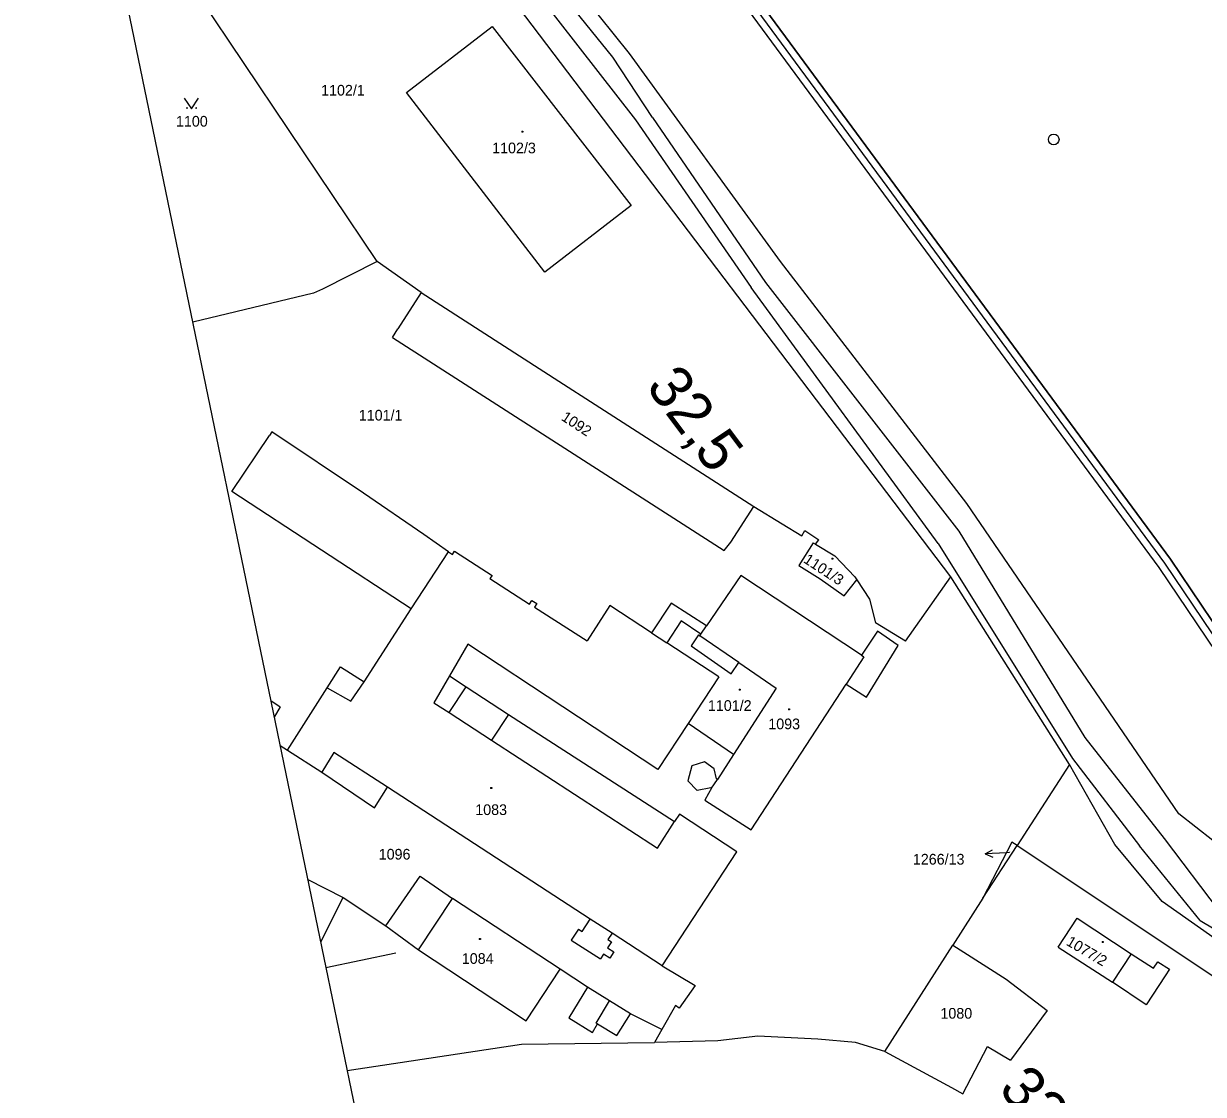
# Model space of a CAD drawing. Extents: x -804166 to -803706, y -1151030 to -1150147.
# Drawn here: x -804166.3 to -804000.6, y -1150430.9 to -1150280.5 of the extents above; entities that cross this region are included whole.
import ezdxf

# ---------------------------------------------------------------- set-up
doc = ezdxf.new("R2010")
doc.units = 0
for name, color, linetype in [('Default', 7, 'Continuous'), ('formát', 7, 'Continuous'), ('kilometráž - vrstava 7', 7, 'Continuous'), ('kn_celek - Cisla parcel pomocna', 7, 'Continuous'), ('kn_celek - Cisla pozemkovych parcel', 7, 'Continuous'), ('kn_celek - Cisla stavebnich parcel', 7, 'Continuous'), ('kn_celek - Hranice parcel', 7, 'Continuous'), ('kn_celek - Vnitrni kresby', 7, 'Continuous'), ('kn_celek - Znacky budov', 7, 'Continuous'), ('kn_celek - Znacky kultur', 7, 'Continuous'), ('plochy - CD', 7, 'Continuous'), ('plochy - VB', 7, 'Continuous'), ('PSR_C2_2_trasa_Vimperk - Kabelová trasa', 7, 'Continuous')]:
    doc.layers.add(name, color=color, linetype=linetype)

# ---------------------------------------------------------------- blocks, each defined once
blk = doc.blocks.new('314')
at = {"layer": 'Default'}
for p, q in [((-10, 15), (0, 0)), ((0, 0), (10, 15))]:
    blk.add_line(p, q, dxfattribs=at)
for centre, start, end in [((-6.2, 1), 360, 180), ((-6.2, 1), 180, 360), ((6.6, 1), 0, 180), ((6.6, 1), 180, 0)]:
    blk.add_arc(centre, 0.5, start, end, dxfattribs=at)
blk = doc.blocks.new('402')
at = {"layer": 'Default'}
for p, q in [((-0.8, 0.8), (0.7, 0.8)), ((-0.8, 0.8), (-0.8, -0.7)), ((0.7, 0.8), (0.7, -0.7)), ((0.7, -0.7), (-0.8, -0.7))]:
    blk.add_line(p, q, dxfattribs=at)
blk = doc.blocks.new('Z61')
at = {"layer": 'Default'}
for p, q in [((0, 0), (30, 0)), ((30, 0), (19.2, 5.3)), ((30, 0), (19.2, -5.3))]:
    blk.add_line(p, q, dxfattribs=at)

msp = doc.modelspace()

# ---------------------------------------------------------------- linework, layer by layer
at = {"layer": 'formát'}
for p, q in [((-804166.3, -1150207.4), (-804123.84, -1150413.06)), ((-804123.84, -1150413.06), (-804114.04, -1150411.04)), ((-804123.84, -1150413.06), (-804081.38, -1150618.72))]:
    msp.add_line(p, q, dxfattribs=at)
at = {"layer": 'kilometráž - vrstava 7'}
msp.add_circle((-804021.64, -1150296.75), 0.75, dxfattribs=at)
at = {"layer": 'kn_celek - Cisla parcel pomocna'}
msp.add_line((-804027.84, -1150396.94), (-804028.28, -1150396.96), dxfattribs=at)
at = {"layer": 'kn_celek - Hranice parcel'}
for p, q in [((-804081.21, -1150284.7), (-804121.35, -1150234.4)), ((-804116.64, -1150313.9), (-804155.03, -1150256.65)), ((-804036.11, -1150358.19), (-804098.91, -1150275.35)), ((-804112.54, -1150290.16), (-804100.49, -1150280.89)), ((-804100.49, -1150280.89), (-804080.97, -1150306.02)), ((-804060.01, -1150313.9), (-804081.21, -1150284.7)), ((-804093.08, -1150315.42), (-804112.54, -1150290.16)), ((-804080.97, -1150306.02), (-804093.08, -1150315.42)), ((-804116.64, -1150313.9), (-804124.3, -1150317.79)), ((-804110.46, -1150318.24), (-804116.64, -1150313.9)), ((-804033.86, -1150347.88), (-804060.01, -1150313.9)), ((-804124.3, -1150317.79), (-804125.6, -1150318.34)), ((-804125.6, -1150318.34), (-804142.55, -1150322.43)), ((-804110.46, -1150318.24), (-804113.74, -1150323.38)), ((-804110.46, -1150318.24), (-804090.5, -1150331.11)), ((-804114.51, -1150324.58), (-804113.74, -1150323.38)), ((-804114.51, -1150324.58), (-804067.92, -1150354.52)), ((-804090.5, -1150331.11), (-804086.7, -1150333.56)), ((-804086.7, -1150333.56), (-804063.77, -1150348.34)), ((-804137.05, -1150346.23), (-804131.77, -1150338.33)), ((-804131.45, -1150337.85), (-804131.77, -1150338.33)), ((-804118.57, -1150346.46), (-804131.45, -1150337.85)), ((-804111.88, -1150362.71), (-804137.05, -1150346.23)), ((-804110.08, -1150352.27), (-804118.57, -1150346.46)), ((-804066.98, -1150353.34), (-804063.77, -1150348.34)), ((-804063.77, -1150348.34), (-804059.77, -1150350.77)), ((-804004.05, -1150391.51), (-804033.86, -1150347.88)), ((-804059.77, -1150350.77), (-804057.02, -1150352.44)), ((-804106.65, -1150354.7), (-804110.08, -1150352.27)), ((-804057.02, -1150352.44), (-804056.61, -1150351.71)), ((-804056.61, -1150351.71), (-804054.61, -1150353.01)), ((-804067.92, -1150354.52), (-804066.98, -1150353.34)), ((-804055.41, -1150353.41), (-804057.43, -1150356.6)), ((-804055.41, -1150353.41), (-804055.07, -1150353.62)), ((-804055.07, -1150353.62), (-804054.61, -1150353.01)), ((-804055.07, -1150353.62), (-804052.39, -1150355.25)), ((-804106.65, -1150354.7), (-804106.08, -1150355.06)), ((-804106.08, -1150355.06), (-804105.79, -1150354.6)), ((-804105.79, -1150354.6), (-804100.51, -1150357.99)), ((-804049.55, -1150358.18), (-804052.39, -1150355.25)), ((-804057.43, -1150356.6), (-804054.44, -1150358.5)), ((-804100.51, -1150357.99), (-804100.81, -1150358.45)), ((-804100.81, -1150358.45), (-804095.25, -1150362.02)), ((-804065.57, -1150358), (-804070.4, -1150365.1)), ((-804048.65, -1150369.22), (-804065.57, -1150358)), ((-804054.44, -1150358.5), (-804051.06, -1150360.86)), ((-804051.06, -1150360.86), (-804049.27, -1150358.61)), ((-804049.55, -1150358.18), (-804049.27, -1150358.61)), ((-804049.27, -1150358.61), (-804047.52, -1150361.32)), ((-804042.43, -1150367.25), (-804036.11, -1150358.19)), ((-804019.43, -1150384.54), (-804036.11, -1150358.19)), ((-804095.25, -1150362.02), (-804094.92, -1150361.51)), ((-804094.92, -1150361.51), (-804094.22, -1150361.96)), ((-804094.22, -1150361.96), (-804094.55, -1150362.47)), ((-804094.55, -1150362.47), (-804087.17, -1150367.2)), ((-804083.95, -1150362.23), (-804087.17, -1150367.2)), ((-804078.13, -1150366.07), (-804083.95, -1150362.23)), ((-804075.36, -1150361.89), (-804078.13, -1150366.07)), ((-804070.4, -1150365.1), (-804075.36, -1150361.89)), ((-804047.52, -1150361.32), (-804046.65, -1150364.68)), ((-804118.45, -1150372.97), (-804111.88, -1150362.71)), ((-804071.18, -1150366.26), (-804070.4, -1150365.1)), ((-804046.4, -1150365.83), (-804048.65, -1150369.22)), ((-804042.43, -1150367.25), (-804046.65, -1150364.68)), ((-804043.46, -1150367.86), (-804046.4, -1150365.83)), ((-804078.13, -1150366.07), (-804075.97, -1150367.48)), ((-804068.66, -1150372.26), (-804075.97, -1150367.48)), ((-804071.53, -1150366.35), (-804072.53, -1150367.9)), ((-804071.53, -1150366.35), (-804071.33, -1150366.49)), ((-804071.33, -1150366.49), (-804071.18, -1150366.26)), ((-804103.93, -1150367.66), (-804106.49, -1150372.1)), ((-804077.23, -1150385.27), (-804103.93, -1150367.66)), ((-804072.53, -1150367.9), (-804066.93, -1150371.81)), ((-804047.95, -1150375.09), (-804043.46, -1150367.86)), ((-804123.67, -1150373.78), (-804121.79, -1150370.84)), ((-804121.79, -1150370.84), (-804118.45, -1150372.97)), ((-804066.93, -1150371.81), (-804065.85, -1150370.25)), ((-804065.85, -1150370.25), (-804060.62, -1150373.84)), ((-804106.49, -1150372.1), (-804104.14, -1150373.65)), ((-804068.66, -1150372.26), (-804072.97, -1150378.81)), ((-804129.25, -1150382.55), (-804123.67, -1150373.78)), ((-804104.14, -1150373.65), (-804098.21, -1150377.56)), ((-804060.62, -1150373.84), (-804066.6, -1150383.18)), ((-804064.14, -1150393.75), (-804050.8, -1150373.27)), ((-804050.8, -1150373.27), (-804047.95, -1150375.09)), ((-804131.58, -1150375.58), (-804130.27, -1150376.47)), ((-804130.27, -1150376.47), (-804131.1, -1150377.9)), ((-804098.21, -1150377.56), (-804074.88, -1150392.59)), ((-804072.97, -1150378.81), (-804077.23, -1150385.27)), ((-804066.6, -1150383.18), (-804072.97, -1150378.81)), ((-804130.27, -1150381.91), (-804129.25, -1150382.55)), ((-804129.25, -1150382.55), (-804124.41, -1150385.63)), ((-804070.69, -1150384.19), (-804072.47, -1150384.76)), ((-804069.32, -1150385.17), (-804070.69, -1150384.19)), ((-804066.6, -1150383.18), (-804068.84, -1150386.68)), ((-804124.41, -1150385.63), (-804117.01, -1150390.65)), ((-804072.47, -1150384.76), (-804073.03, -1150386.88)), ((-804068.99, -1150386.56), (-804069.32, -1150385.17)), ((-804019.43, -1150384.54), (-804026.79, -1150395.95)), ((-804013.04, -1150395.78), (-804019.43, -1150384.54)), ((-804073.03, -1150386.88), (-804071.69, -1150388.23)), ((-804068.84, -1150386.68), (-804068.99, -1150386.56)), ((-804117.01, -1150390.65), (-804115.18, -1150387.77)), ((-804086.74, -1150406.28), (-804115.18, -1150387.77)), ((-804069.79, -1150387.85), (-804071.69, -1150388.23)), ((-804070.1, -1150388.62), (-804070.63, -1150389.59)), ((-804069.7, -1150387.9), (-804070.1, -1150388.62)), ((-804069.79, -1150387.85), (-804069.7, -1150387.9)), ((-804070.63, -1150389.59), (-804064.14, -1150393.75)), ((-804074.21, -1150391.55), (-804074.88, -1150392.59)), ((-804066.12, -1150396.82), (-804074.21, -1150391.55)), ((-803965.92, -1150421.41), (-804004.05, -1150391.51)), ((-804027.51, -1150395.47), (-804031.57, -1150403.35)), ((-804026.79, -1150395.95), (-804027.51, -1150395.47)), ((-804006.42, -1150403.82), (-804013.04, -1150395.78)), ((-804076.63, -1150412.86), (-804066.12, -1150396.82)), ((-804031.57, -1150403.35), (-804026.79, -1150395.95)), ((-804026.79, -1150395.95), (-803971.47, -1150432.84)), ((-804126.38, -1150400.74), (-804121.43, -1150403.27)), ((-804115.43, -1150407.21), (-804110.61, -1150400.26)), ((-804110.61, -1150400.26), (-804106.05, -1150403.38)), ((-804121.43, -1150403.27), (-804115.43, -1150407.21)), ((-804090.94, -1150413.32), (-804106.05, -1150403.38)), ((-804031.57, -1150403.35), (-804035.79, -1150409.93)), ((-803984.95, -1150418.93), (-804006.42, -1150403.82)), ((-804087.86, -1150408.01), (-804086.74, -1150406.28)), ((-804021.01, -1150410.24), (-804018.34, -1150406.17)), ((-804018.34, -1150406.17), (-804010.77, -1150411.14)), ((-804088.38, -1150407.69), (-804089.38, -1150409.22)), ((-804088.38, -1150407.69), (-804087.86, -1150408.01)), ((-804083.66, -1150408.28), (-804084.25, -1150409.15)), ((-804076.63, -1150412.86), (-804083.66, -1150408.28)), ((-804089.38, -1150409.22), (-804085.28, -1150411.85)), ((-804083.76, -1150409.47), (-804084.3, -1150410.32)), ((-804084.3, -1150410.32), (-804083.42, -1150410.88)), ((-804084.25, -1150409.15), (-804083.76, -1150409.47)), ((-804045.36, -1150424.86), (-804035.79, -1150409.93)), ((-804035.79, -1150409.93), (-804034.24, -1150410.92)), ((-804021.01, -1150410.24), (-804013.4, -1150415.15)), ((-804084.86, -1150411.19), (-804085.28, -1150411.85)), ((-804083.98, -1150411.75), (-804084.86, -1150411.19)), ((-804083.42, -1150410.88), (-804083.98, -1150411.75)), ((-804034.24, -1150410.92), (-804028.34, -1150414.7)), ((-804010.77, -1150411.14), (-804007.61, -1150413.19)), ((-804007.61, -1150413.19), (-804007.01, -1150412.27)), ((-804007.01, -1150412.27), (-804005.4, -1150413.32)), ((-804087.12, -1150415.83), (-804090.94, -1150413.32)), ((-804076.63, -1150412.86), (-804071.97, -1150415.6)), ((-804005.4, -1150413.32), (-804006.01, -1150414.26)), ((-804071.97, -1150415.6), (-804074.24, -1150418.81)), ((-804028.34, -1150414.7), (-804022.57, -1150419.14)), ((-804008.66, -1150418.32), (-804013.4, -1150415.15)), ((-804006.01, -1150414.26), (-804008.66, -1150418.32)), ((-804084, -1150417.78), (-804087.12, -1150415.83)), ((-804081.08, -1150419.61), (-804084, -1150417.78)), ((-804074.74, -1150418.43), (-804076.66, -1150421.77)), ((-804074.24, -1150418.81), (-804074.74, -1150418.43)), ((-804076.66, -1150421.77), (-804081.08, -1150419.61)), ((-804022.57, -1150419.14), (-804027.7, -1150426.08)), ((-804076.66, -1150421.77), (-804077.72, -1150423.61)), ((-804120.85, -1150427.56), (-804096.4, -1150423.85)), ((-804096.4, -1150423.85), (-804077.72, -1150423.61)), ((-804068.82, -1150423.37), (-804077.72, -1150423.61)), ((-804063.18, -1150422.75), (-804068.82, -1150423.37)), ((-804054.77, -1150423.16), (-804063.18, -1150422.75)), ((-804049.48, -1150423.64), (-804054.77, -1150423.16)), ((-804045.36, -1150424.86), (-804049.48, -1150423.64)), ((-804045.36, -1150424.86), (-804035.98, -1150429.93)), ((-804034.39, -1150430.82), (-804030.93, -1150424.18)), ((-804030.93, -1150424.18), (-804027.7, -1150426.08)), ((-804035.98, -1150429.93), (-804034.39, -1150430.82))]:
    msp.add_line(p, q, dxfattribs=at)
at = {"layer": 'kn_celek - Vnitrni kresby'}
for p, q in [((-804105.26, -1150261.99), (-804080.36, -1150294)), ((-804083.56, -1150285.18), (-804101.97, -1150262.44)), ((-804077.99, -1150293.67), (-804083.56, -1150285.18)), ((-804080.36, -1150294), (-804064.13, -1150317.57)), ((-804077.99, -1150293.67), (-804062.09, -1150316.83)), ((-804037.88, -1150353.52), (-804064.13, -1150317.57)), ((-804062.09, -1150316.83), (-804034.98, -1150351.76)), ((-804034.98, -1150351.76), (-804017.28, -1150380.76)), ((-804037.88, -1150353.52), (-804018.99, -1150383.74)), ((-804111.88, -1150362.71), (-804106.65, -1150354.7)), ((-804073.97, -1150364.38), (-804075.97, -1150367.48)), ((-804071.18, -1150366.26), (-804073.97, -1150364.38)), ((-804065.85, -1150370.25), (-804071.33, -1150366.49)), ((-804048.65, -1150369.22), (-804048.3, -1150369.42)), ((-804048.3, -1150369.42), (-804050.8, -1150373.27)), ((-804106.49, -1150372.1), (-804108.67, -1150375.88)), ((-804123.67, -1150373.78), (-804120.36, -1150375.68)), ((-804120.36, -1150375.68), (-804118.45, -1150372.97)), ((-804106.53, -1150377.27), (-804104.14, -1150373.65)), ((-804108.67, -1150375.88), (-804106.53, -1150377.27)), ((-804106.53, -1150377.27), (-804100.6, -1150381.13)), ((-804098.21, -1150377.56), (-804100.6, -1150381.13)), ((-804017.28, -1150380.76), (-804006.14, -1150394.97)), ((-804100.6, -1150381.13), (-804077.27, -1150396.34)), ((-804122.71, -1150382.87), (-804124.41, -1150385.63)), ((-804115.18, -1150387.77), (-804122.71, -1150382.87)), ((-804018.99, -1150383.74), (-804009.57, -1150396.01)), ((-804069.7, -1150387.9), (-804068.84, -1150386.68)), ((-804077.27, -1150396.34), (-804074.88, -1150392.59)), ((-804006.14, -1150394.97), (-803998.39, -1150405.19)), ((-804001.06, -1150406.5), (-804009.57, -1150396.01)), ((-804124.58, -1150409.47), (-804121.43, -1150403.27)), ((-804110.84, -1150410.62), (-804106.05, -1150403.38)), ((-804115.43, -1150407.21), (-804110.84, -1150410.62)), ((-804083.66, -1150408.28), (-804086.74, -1150406.28)), ((-804001.06, -1150406.5), (-803969.03, -1150425.49)), ((-804110.84, -1150410.62), (-804095.74, -1150420.57)), ((-804010.77, -1150411.14), (-804013.4, -1150415.15)), ((-804095.74, -1150420.57), (-804090.94, -1150413.32)), ((-804087.12, -1150415.83), (-804089.73, -1150420.16)), ((-804085.87, -1150420.89), (-804084, -1150417.78)), ((-804089.73, -1150420.16), (-804086.42, -1150422.23)), ((-804083, -1150422.63), (-804081.08, -1150419.61)), ((-804086.42, -1150422.23), (-804085.72, -1150420.98)), ((-804085.72, -1150420.98), (-804085.87, -1150420.89)), ((-804085.72, -1150420.98), (-804083, -1150422.63))]:
    msp.add_line(p, q, dxfattribs=at)
at = {"layer": 'plochy - CD'}
for p, q in [((-804078.87, -1150259.13), (-804006.89, -1150356.88)), ((-804005.25, -1150355.72), (-804076.08, -1150259.54))]:
    msp.add_line(p, q, dxfattribs=at)
for points in [[(-803976.88, -1150394.8), (-803989.28, -1150379.42), (-804005.25, -1150355.72)], [(-804006.89, -1150356.88), (-803990.89, -1150380.61), (-803978.48, -1150396)]]:
    msp.add_lwpolyline(points, dxfattribs=at)
at = {"layer": 'plochy - VB'}
for p, q in [((-804078.87, -1150259.13), (-804006.89, -1150356.88)), ((-804076.08, -1150259.54), (-804005.25, -1150355.72))]:
    msp.add_line(p, q, dxfattribs=at)
for points in [[(-804005.25, -1150355.72), (-803989.28, -1150379.42), (-803976.88, -1150394.8)], [(-804006.89, -1150356.88), (-803990.89, -1150380.61), (-803978.48, -1150396)]]:
    msp.add_lwpolyline(points, dxfattribs=at)
at = {"layer": 'PSR_C2_2_trasa_Vimperk - Kabelová trasa'}
msp.add_line((-804077.48, -1150259.34), (-804006.07, -1150356.3), dxfattribs=at)
msp.add_lwpolyline([(-804006.07, -1150356.3), (-803990.08, -1150380.01), (-803977.68, -1150395.4)], dxfattribs=at)

# ---------------------------------------------------------------- block references
at = {"layer": 'kn_celek - Cisla parcel pomocna', "xscale": 0.10000000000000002, "yscale": 0.1, "rotation": -177.0048}
msp.add_blockref('Z61', (-804028.28, -1150396.96), dxfattribs=at)
at = {"layer": 'kn_celek - Znacky budov', "xscale": 0.1, "yscale": 0.10000000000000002}
for p in [(-804096.24, -1150295.65), (-804052.71, -1150355.64), (-804065.73, -1150374.07), (-804058.81, -1150376.82), (-804100.63, -1150387.88), (-804102.22, -1150409.07), (-804014.77, -1150409.52)]:
    msp.add_blockref('402', p, dxfattribs=at)
at = {"layer": 'kn_celek - Znacky kultur', "xscale": 0.1, "yscale": 0.10000000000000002}
msp.add_blockref('314', (-804142.73, -1150292.44), dxfattribs=at)

# ---------------------------------------------------------------- texts
at = {"layer": 'kilometráž - vrstava 7'}
for s, rotation, p in [('32,5', 306.9651, (-804079.02, -1150331.49)), ('32,6', 311.8828, (-804029.55, -1150430.27))]:
    msp.add_text(s, height=6, rotation=rotation, dxfattribs=at).set_placement(p)
at = {"layer": 'kn_celek - Cisla parcel pomocna'}
msp.add_text('1266/13', height=1.5, dxfattribs=at).set_placement((-804041.42, -1150398.62))
at = {"layer": 'kn_celek - Cisla pozemkovych parcel'}
for s, height, p in [('1102/1', 1.5, (-804124.52, -1150290.59)), ('1100', 1.5, (-804144.9, -1150294.95)), ('1101/1', 1.5, (-804119.23, -1150336.24)), ('1096', 1.5, (-804116.43, -1150397.92)), ('1266/13', 0.1, (-804027.84, -1150396.91)), ('1080', 1.5, (-804037.55, -1150420.27))]:
    msp.add_text(s, height=height, dxfattribs=at).set_placement(p)
msp.add_text('1092', height=1.5, rotation=326.7, dxfattribs=at).set_placement((-804090.91, -1150336.1))
at = {"layer": 'kn_celek - Cisla stavebnich parcel'}
for s, p in [('1102/3', (-804100.5, -1150298.7)), ('1101/2', (-804070.2, -1150377.03)), ('1093', (-804061.72, -1150379.61)), ('1083', (-804102.87, -1150391.66)), ('1084', (-804104.76, -1150412.57))]:
    msp.add_text(s, height=1.5, dxfattribs=at).set_placement(p)
for s, rotation, p in [('1101/3', 326.7, (-804056.89, -1150356.1)), ('1077/2', 329.4, (-804020, -1150409.85))]:
    msp.add_text(s, height=1.5, rotation=rotation, dxfattribs=at).set_placement(p)

doc.saveas('drawing.dxf')
